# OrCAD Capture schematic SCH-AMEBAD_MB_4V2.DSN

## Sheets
1 P1_DC Power: size Custom; title: ARMEBA_MB; rev: 1.0; note: DC Power
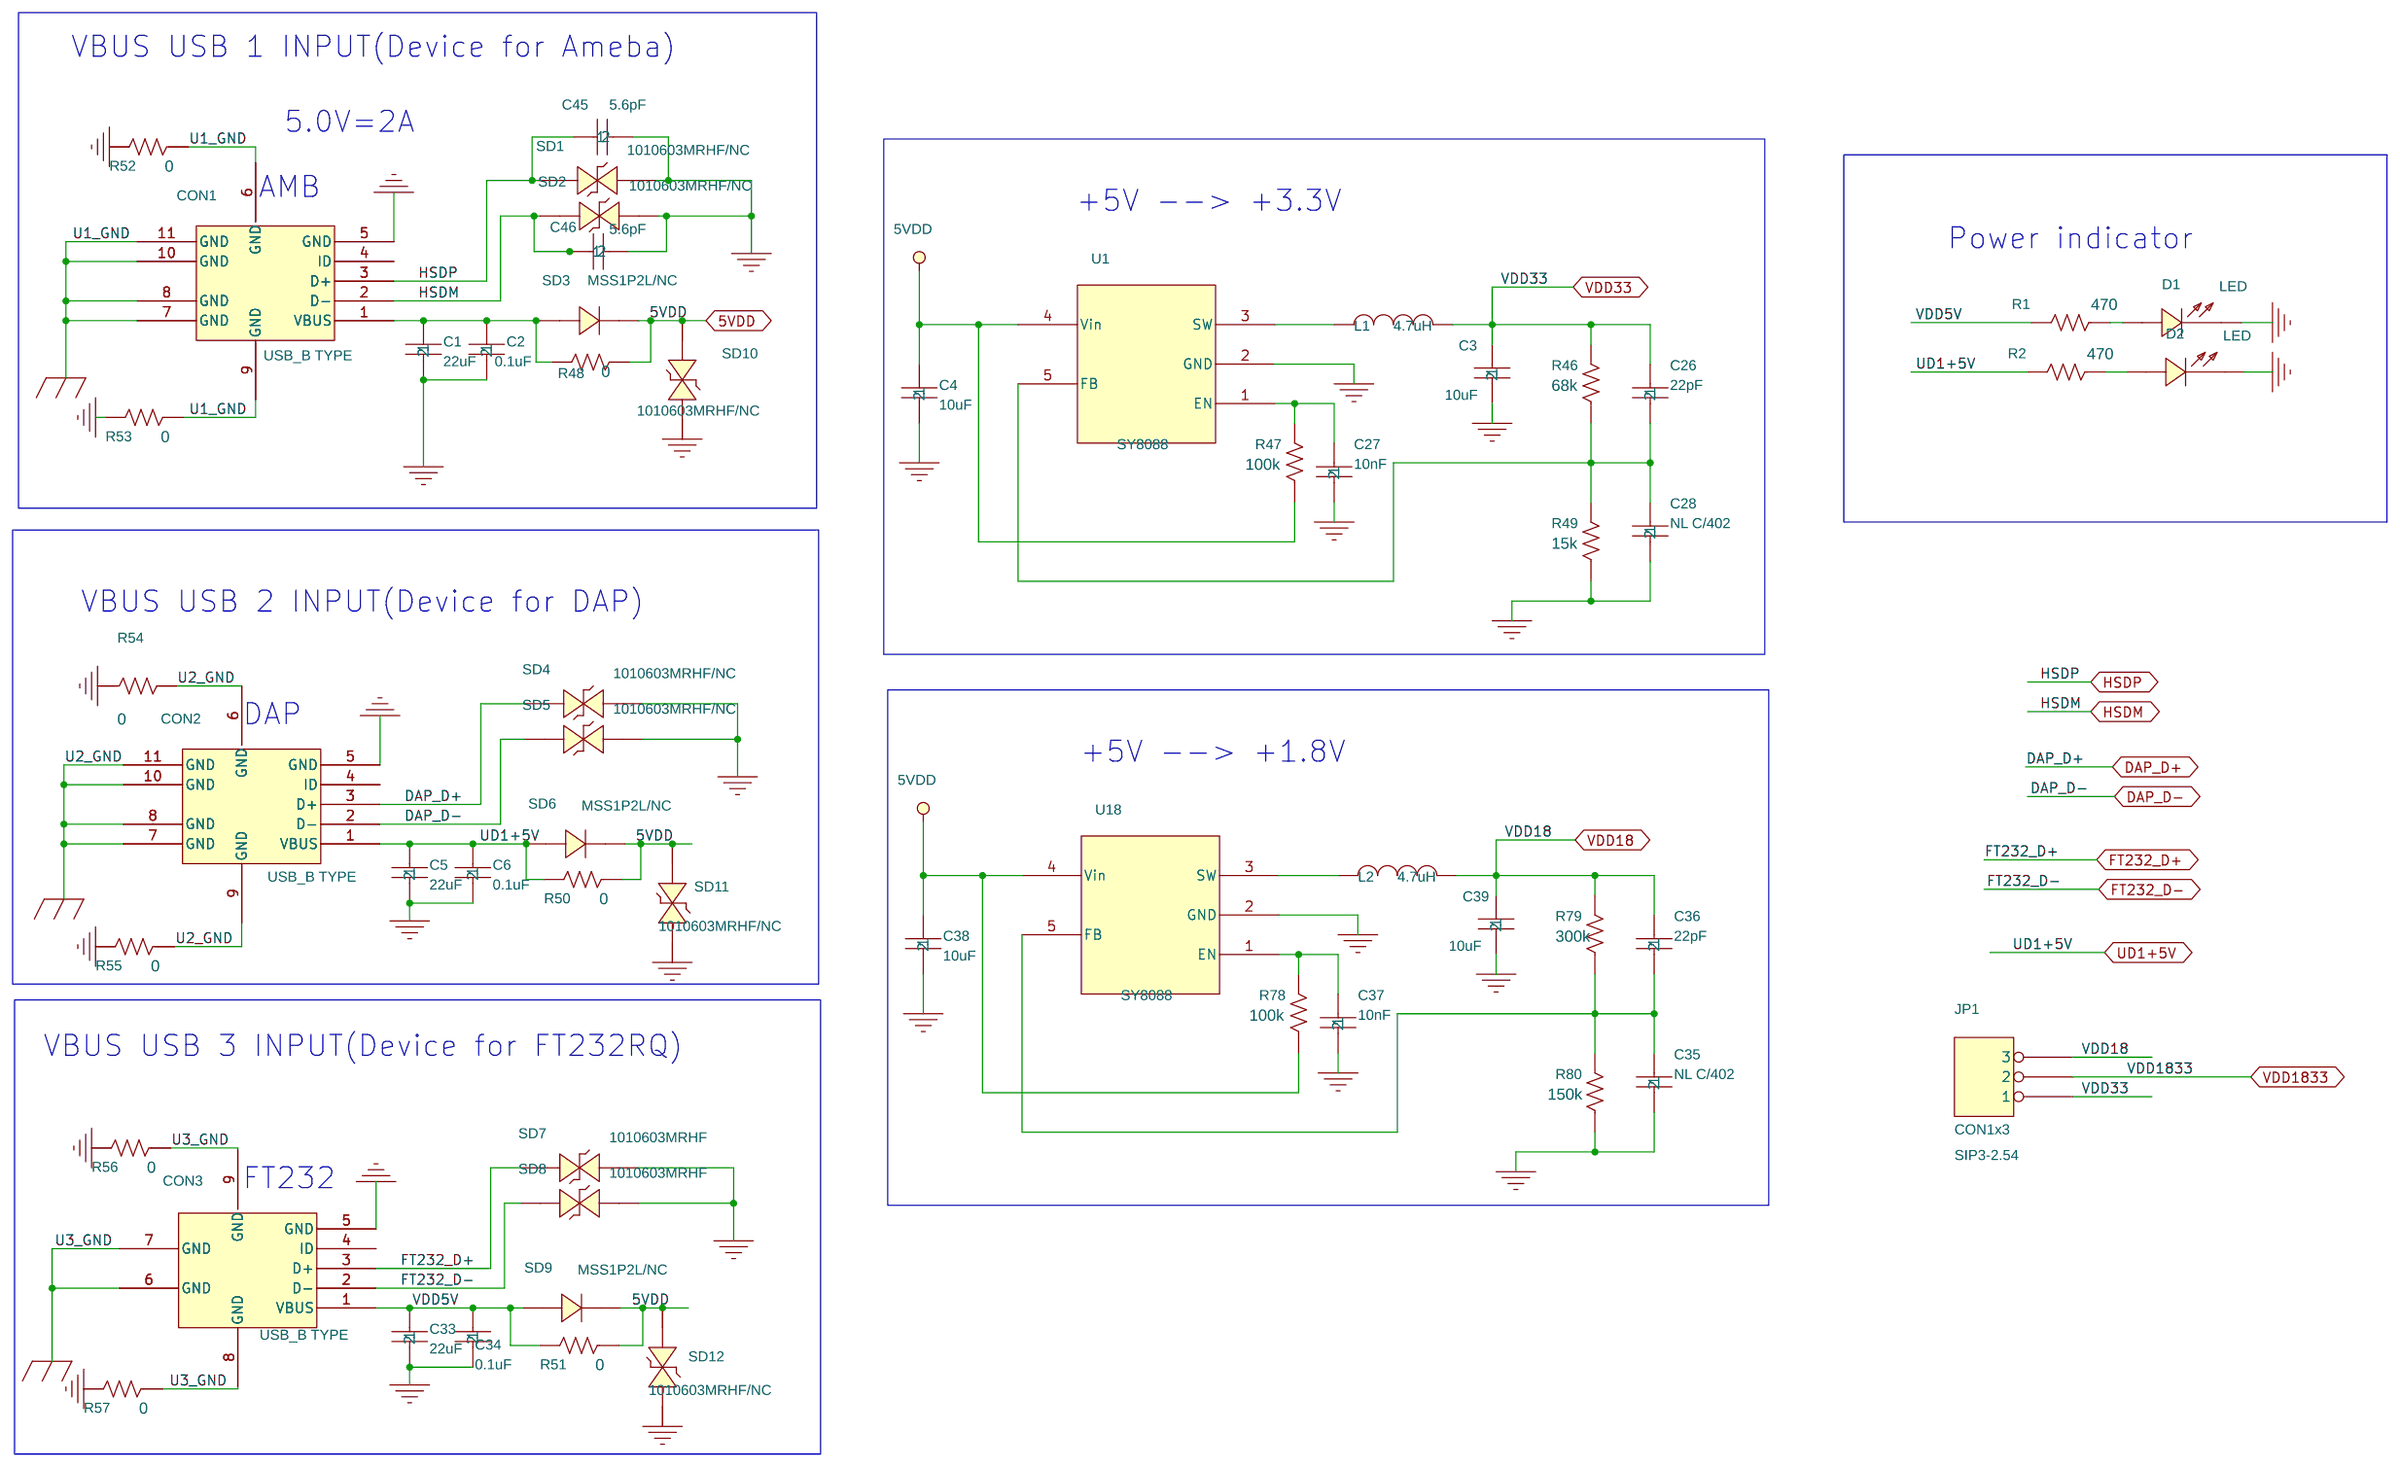
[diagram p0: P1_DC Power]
2 P2_Main: size Custom; title: ARDUINO; note: DAP/Ameba
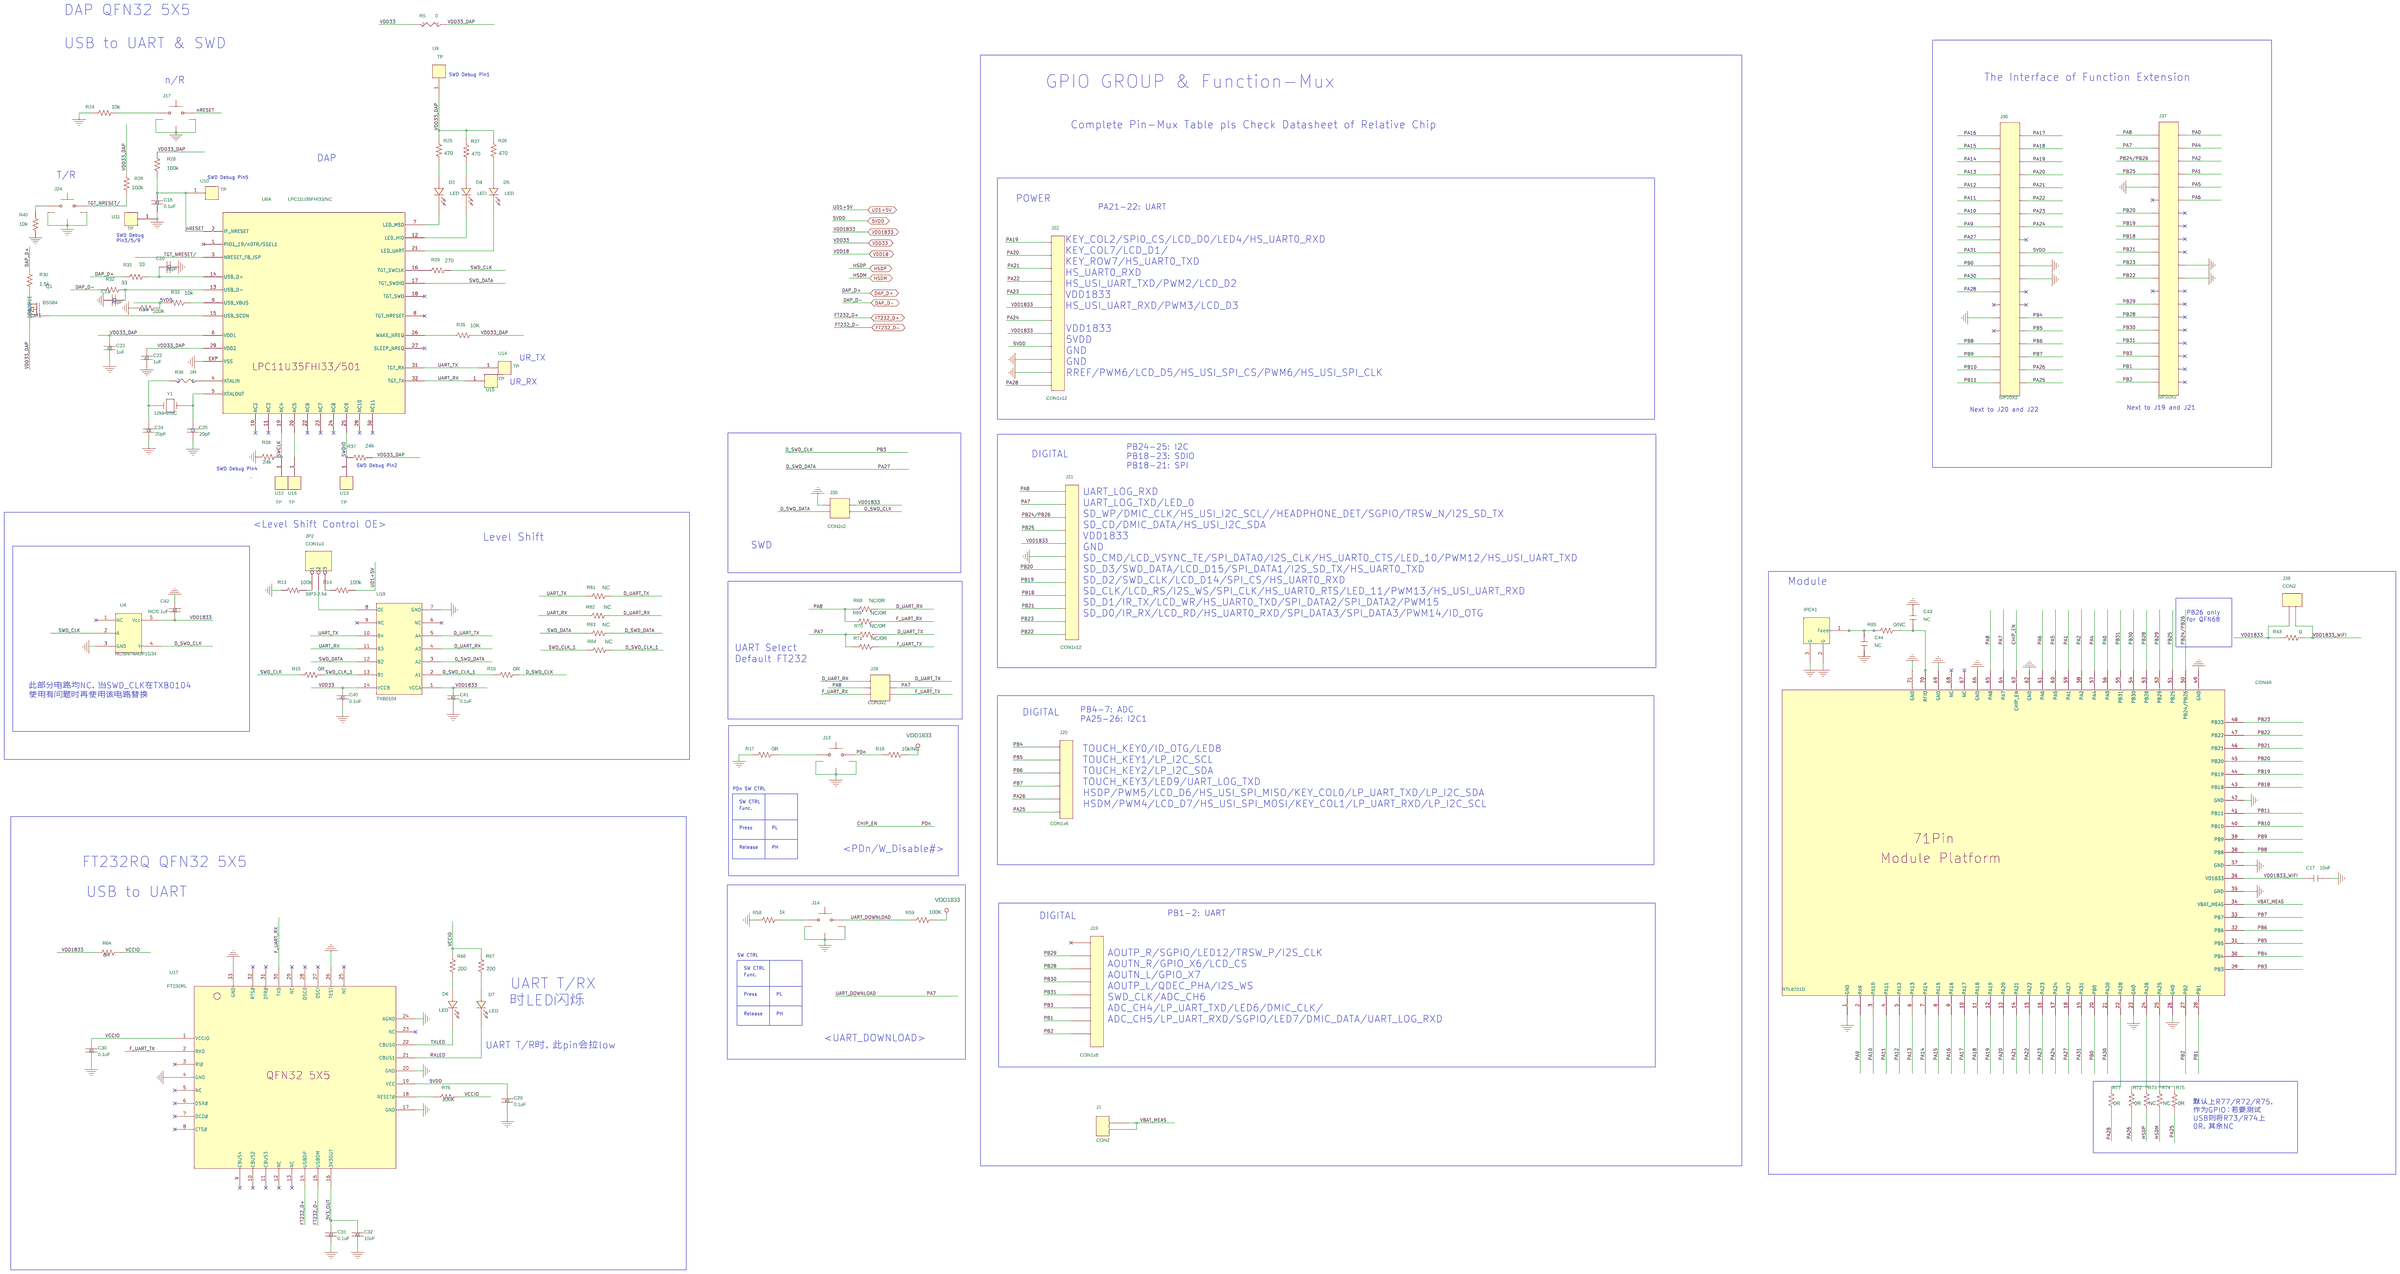
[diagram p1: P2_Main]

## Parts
sheet P1_DC Power
C1  22uF  [C0603]
C2  0.1uF  [C0402]
C3  10uF  [C0603]
C4  10uF  [C0603]
C5  22uF  [C0603]
C6  0.1uF  [C0402]
C26  22pF  [C0402]
C27  10nF  [C0402]
C28  NL C/402  [C0402]
C33  22uF  [C0603]
C34  0.1uF  [C0402]
C35  NL C/402  [C0402]
C36  22pF  [C0402]
C37  10nF  [C0402]
C38  10uF  [C0603]
C39  10uF  [C0603]
C45  5.6pF  [C0402]
C46  5.6pF  [C0402]
CON1  USB_B TYPE  [USB-MICRO-B-SMT-3]
CON2  USB_B TYPE  [USB-MICRO-B-SMT-3]
CON3  USB_B TYPE  [USB-MICRO-B-SMT-3]
D1  LED  [LED-0603]
D2  LED  [LED-0603]
JP1  CON1x3  [SIP3-2.54]
L1  4.7uH  [L3030]
L2  4.7uH  [L3030]
R1  470  [R0402]
R2  470  [R0402]
R46  68k  [R0402]
R47  100k  [R0402]
R48  0  [R0805]
R49  15k  [R0402]
R50  0  [R0805]
R51  0  [R0805]
R52  0  [R0603]
R53  0  [R0603]
R54  0  [R0603]
R55  0  [R0603]
R56  0  [R0603]
R57  0  [R0603]
R78  100k  [R0402]
R79  300k  [R0402]
R80  150k  [R0402]
SD1  1010603MRHF/NC  [L0603]
SD2  1010603MRHF/NC  [L0603]
SD3  MSS1P2L/NC  [MICROSMP]
SD4  1010603MRHF/NC  [L0603]
SD5  1010603MRHF/NC  [L0603]
SD6  MSS1P2L/NC  [MICROSMP]
SD7  1010603MRHF  [L0603]
SD8  1010603MRHF  [L0603]
SD9  MSS1P2L/NC  [MICROSMP]
SD10  1010603MRHF/NC  [L0603]
SD11  1010603MRHF/NC  [L0603]
SD12  1010603MRHF/NC  [L0603]
U1  SY8088  [SOT-23-5]
U18  SY8088  [SOT-23-5]
sheet P2_Main
C17  10uF  [C0603]
C18  0.1uF  [C0402]
C20  22pF  [C0402]
C21  22pF  [C0402]
C22  1uF  [C0402]
C23  1uF  [C0402]
C24  20pF  [C0402]
C25  20pF  [C0402]
C29  0.1uF  [C0402]
C30  0.1uF  [C0402]
C31  0.1uF  [C0402]
C32  10uF  [C0603]
C40  0.1uF  [C0402]
C41  0.1uF  [C0402]
C42  NC/0.1uF  [C0402]
C43  NC  [C0402]
C44  NC  [C0402]
CON4  RTL8721D  [71PIN-MODULE-PLATFORM]  (section A)
D3  LED  [LED-0603]
D4  LED  [LED-0603]
D5  LED  [LED-0603]
D6  LED  [LED-0603]
D7  LED  [LED-0603]
IPEX1  TP  [IPEX-0.7X2.2-1.35]
J1  CON2  [SIP2-2.54]
J13  Reset Button  [SW5-4.65X2.3-H1.85]
J14  Reset Button  [SW5-4.65X2.3-H1.85]
J17  Reset Button  [SW5-4.65X2.3-H1.85]
J19  CON1x8  [SIP8-2.54]
J20  CON1x6  [SIP6-2.54]
J21  CON1x12  [SIP12-2.54]
J22  CON1x12  [SIP12-2.54]
J24  Reset Button  [SW5-4.65X2.3-H1.85]
J28  CON3x2  [SIP3X2-2.54]
J35  CON2x2  [SIP2X2-2.54]
J36  SIP20X2  [SIP20X2-2.54]
J37  SIP20X2  [SIP20X2-2.54]
J38  CON2  [SIP2-2.54]
JP2  CON1x3  [SIP3-2.54]
Q1  BSS84  [SOT-23-GDS]
R5  0  [R0603]
R13  100k  [R0402]
R14  100k  [R0402]
R15  0R  [R0402]
R16  0R  [R0402]
R17  0R  [R0402]
R18  10k/NC  [R0402]
R24  10k  [R0402]
R25  470  [R0402]
R26  470  [R0402]
R27  470  [R0402]
R28  100k  [R0402]
R29  270  [R0402]
R30  1.5k  [R0402]
R31  33  [R0402]
R32  33  [R0402]
R33  10k  [R0402]
R34  100k  [R0402]
R35  10K  [R0402]
R36  0R  [R0402]
R37  24k  [R0402]
R38  24k  [R0402]
R39  100k  [R0402]
R40  10k  [R0402]
R43  0  [R0603]
R58  1k  [R0402]
R59  100K  [R0402]
R64  0R  [R0402]
R66  200  [R0402]
R67  200  [R0402]
R68  NC/0R  [R0402]
R69  NC/0R  [R0402]
R70  NC/0R  [R0402]
R71  NC/0R  [R0402]
R72  0R  [R0402]
R73  NC  [R0402]
R74  NC  [R0402]
R75  0R  [R0402]
R76  100K  [R0402]
R77  0R  [R0402]
R81  NC  [R0402]
R82  NC  [R0402]
R83  NC  [R0402]
R84  NC  [R0402]
R85  0/NC  [R0402]
U4  NC/SN74AUP1G34  [SOT-23-5]
U8  LPC11U35FHI33/NC  [QFN32-0505-.5-H.85-E3.75]  (section A)
U9  TP  [TP]
U10  TP  [TP]
U11  TP  [TP]
U12  TP  [TP]
U13  TP  [TP]
U14  TP  [TP]
U15  TP  [TP]
U16  TP  [TP]
U17  FT232RL  [QFN32-0.5-5X5-EP3.2]
U19  TXB0104  [SOP14/5.6/0.65]
Y1  12MHz/NC  [XTAL-CRYSTAL]

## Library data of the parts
C1 = C_7: X7R, ∮10%, 10V; Manufacturer: WALSIN; Part Number: 0402B104K100CT; Unit Price(USD): 0.0008
C2 = C_5: X7R, ∮10%, 10V; Manufacturer: WALSIN; Part Number: 0402B104K100CT; Unit Price(USD): 0.0008
C3 = C_6: X7R, ∮10%, 10V; Manufacturer: WALSIN; Part Number: 0402B104K100CT; Unit Price(USD): 0.0008
C4 = C_11: X7R, ∮10%, 10V; Manufacturer: WALSIN; Part Number: 0402B104K100CT; Unit Price(USD): 0.0008
C5 = C: X7R, ∮10%, 10V; Manufacturer: WALSIN; Part Number: 0402B104K100CT; Unit Price(USD): 0.0008
C6 = C_1: X7R, ∮10%, 10V; Manufacturer: WALSIN; Part Number: 0402B104K100CT; Unit Price(USD): 0.0008
C26 = CAP_NP_2: NPO, ∮10%, 25V; Manufacturer: WALSIN; Part Number: 0402B103K250CT; Unit Price(USD): 0.00076
C27 = CAP_NP_4: NPO, ∮10%, 25V; Manufacturer: WALSIN; Part Number: 0402B103K250CT; Unit Price(USD): 0.00076
C28 = CAP_NP_5
C33 = C_8: X7R, ∮10%, 10V; Manufacturer: WALSIN; Part Number: 0402B104K100CT; Unit Price(USD): 0.0008
C34 = C_3: X7R, ∮10%, 10V; Manufacturer: WALSIN; Part Number: 0402B104K100CT; Unit Price(USD): 0.0008
C35 = CAP_NP_3
C36 = CAP_NP_1: NPO, ∮10%, 25V; Manufacturer: WALSIN; Part Number: 0402B103K250CT; Unit Price(USD): 0.00076
C37 = CAP_NP: NPO, ∮10%, 25V; Manufacturer: WALSIN; Part Number: 0402B103K250CT; Unit Price(USD): 0.00076
C38 = C_2: X7R, ∮10%, 10V; Manufacturer: WALSIN; Part Number: 0402B104K100CT; Unit Price(USD): 0.0008
C39 = C_9: X7R, ∮10%, 10V; Manufacturer: WALSIN; Part Number: 0402B104K100CT; Unit Price(USD): 0.0008
C45 = C_10: X7R, ∮10%, 10V; Manufacturer: WALSIN; Part Number: 0402B104K100CT; Unit Price(USD): 0.0008
C46 = C_4: X7R, ∮10%, 10V; Manufacturer: WALSIN; Part Number: 0402B104K100CT; Unit Price(USD): 0.0008
CON1 = USB_CON_1X4P_ACON_2: CONTECK/22133-4W21-01; Class: IO; Colay_Alternate: N/A; Colay_Group: N/A; Component_Name: USB CON 1X4P,M,A TYPE,R/A,SMT; Critical_Part: N; Data_Sheet: K:\DataSheet\12-CONNECTOR\1213-003Q000.zip; Database_Update: 2009/2/7; Device: hh_usb_1x4p_4hd_m_ra_lf3; Electric_SPE: WHITE; FPLIST: hh_usb_1x4p_4hd_m_ra_lf3,usb_1x4p_4hd_m_ra_lf3; Green_HF: GA; HsFlag: A000000000; Manufacture: CONTECK; Modify_data: 2011/11/03; Optional: N/A; Package_Type: SMD; Part Number: 1213-003Q000; Part Type: 12CONNECTOR\USB; Sourcer: ¶À±Ò©ú(LA0803562); Subsystem_ID: N/A; Symbol_pic: K:\Symbol_Pic\12-CONNECTOR\1213-003Q000_MID.zip; metal_fabrication: 000000X100
CON2 = USB_CON_1X4P_ACON_5: CONTECK/22133-4W21-01; Class: IO; Colay_Alternate: N/A; Colay_Group: N/A; Component_Name: USB CON 1X4P,M,A TYPE,R/A,SMT; Critical_Part: N; Data_Sheet: K:\DataSheet\12-CONNECTOR\1213-003Q000.zip; Database_Update: 2009/2/7; Device: hh_usb_1x4p_4hd_m_ra_lf3; Electric_SPE: WHITE; FPLIST: hh_usb_1x4p_4hd_m_ra_lf3,usb_1x4p_4hd_m_ra_lf3; Green_HF: GA; HsFlag: A000000000; Manufacture: CONTECK; Modify_data: 2011/11/03; Optional: N/A; Package_Type: SMD; Part Number: 1213-003Q000; Part Type: 12CONNECTOR\USB; Sourcer: ¶À±Ò©ú(LA0803562); Subsystem_ID: N/A; Symbol_pic: K:\Symbol_Pic\12-CONNECTOR\1213-003Q000_MID.zip; metal_fabrication: 000000X100
CON3 = USB_CON_1X4P_ACON_3: CONTECK/22133-4W21-01; Class: IO; Colay_Alternate: N/A; Colay_Group: N/A; Component_Name: USB CON 1X4P,M,A TYPE,R/A,SMT; Critical_Part: N; Data_Sheet: K:\DataSheet\12-CONNECTOR\1213-003Q000.zip; Database_Update: 2009/2/7; Device: hh_usb_1x4p_4hd_m_ra_lf3; Electric_SPE: WHITE; FPLIST: hh_usb_1x4p_4hd_m_ra_lf3,usb_1x4p_4hd_m_ra_lf3; Green_HF: GA; HsFlag: A000000000; Manufacture: CONTECK; Modify_data: 2011/11/03; Optional: N/A; Package_Type: SMD; Part Number: 1213-003Q000; Part Type: 12CONNECTOR\USB; Sourcer: ¶À±Ò©ú(LA0803562); Subsystem_ID: N/A; Symbol_pic: K:\Symbol_Pic\12-CONNECTOR\1213-003Q000_MID.zip; metal_fabrication: 000000X100
D1-D7 = LED_0
JP1 JP2 = HEADER_3
L1 L2 = L: GTSD32 power inductor; Manufacturer: び护; Part number: NRH2410T-4R7MN; Unit Price(USD): 0.11875
R1 R2 R25-R27 R48 R50-R57 R64 R66 R67 R72-R77 = RES_V: Manufacturer: WALSIN; Part Number: WR04X4700FTL; Unit Price(USD): 0.00032
R46 R49 R79 R80 = RES_V: Manufacturer: WALSIN; Part Number: WR04X3003FTL; Unit Price(USD): 0.00032
R14-R18 R24 R40 R43 R47 R58 R59 R78 R85 = RES_V: Manufacturer: WALSIN; Part Number: WR04X1003FTL; Unit Price(USD): 0.00032
SD1 SD2 SD4 SD5 SD7 SD8 SD10-SD12 = DIODE_SCHOTTKY_1_v2
SD3 SD6 SD9 = DIODE_SCHOTTKY_1
U1 U18 = LT1084-3_0.3
C17 C43 C44 = C_402
C18 = CAP_NP_11: NPO, ∮10%, 50V; Manufacturer: WALSIN; Part Number: 0402B102K500CT; Unit Price(USD): 0.00076
C20 = CAP_NP_6: NPO, ∮10%, 50V; Manufacturer: WALSIN; Part Number: 0402B102K500CT; Unit Price(USD): 0.00076
C21 = CAP_NP_9: NPO, ∮10%, 50V; Manufacturer: WALSIN; Part Number: 0402B102K500CT; Unit Price(USD): 0.00076
C22 = CAP_NP_1: NPO, ∮10%, 50V; Manufacturer: WALSIN; Part Number: 0402B102K500CT; Unit Price(USD): 0.00076
C23 = CAP_NP: NPO, ∮10%, 50V; Manufacturer: WALSIN; Part Number: 0402B102K500CT; Unit Price(USD): 0.00076
C24 = C_1: NPO, ∮5%, 50V; Manufacturer: WALSIN; Part Number: 0402N180J500LT; Unit Price(USD): 0.00076
C25 = C: NPO, ∮5%, 50V; Manufacturer: WALSIN; Part Number: 0402N180J500LT; Unit Price(USD): 0.00076
C29 = CAP_NP_10: NPO, ∮10%, 50V; Manufacturer: WALSIN; Part Number: 0402B102K500CT; Unit Price(USD): 0.00076
C30 = CAP_NP_5: NPO, ∮10%, 50V; Manufacturer: WALSIN; Part Number: 0402B102K500CT; Unit Price(USD): 0.00076
C31 = CAP_NP_4: NPO, ∮10%, 50V; Manufacturer: WALSIN; Part Number: 0402B102K500CT; Unit Price(USD): 0.00076
C32 = CAP_NP_7: NPO, ∮10%, 50V; Manufacturer: WALSIN; Part Number: 0402B102K500CT; Unit Price(USD): 0.00076
C40 = CAP_NP_3: NPO, ∮10%, 50V; Manufacturer: WALSIN; Part Number: 0402B102K500CT; Unit Price(USD): 0.00076
C41 = CAP_NP_8: NPO, ∮10%, 50V; Manufacturer: WALSIN; Part Number: 0402B102K500CT; Unit Price(USD): 0.00076
C42 = CAP_NP_2: NPO, ∮10%, 50V; Manufacturer: WALSIN; Part Number: 0402B102K500CT; Unit Price(USD): 0.00076
CON4 = 8723BS_9
IPEX1 = TP_3
J1 J38 = CON2
J13 J14 J17 J24 = BUTTON_(RST)_1
J19 = CON6_4
J20 = CON6_3
J21 J22 = CON6_0
J28 = CON6_2
J35 = CON6_5
J36 J37 = CON6_10
Q1 = MOSFET_P_DGS_0
R5 = R
R13 R28-R35 R37-R39 R68-R71 R81-R84 = RES_V: Manufacturer: WALSIN; Part Number: WR04X1002FTL; Unit Price(USD): 0.00032
R36 = R_1
U4 = 2N7002DW_1
U8 = 8723BS_6
U9-U16 = TP
U17 = RL5760_0
U19 = 2N7002DW_3
Y1 = CRYSTAL_0

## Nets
3V3_OUT: C31.1 C32.1 U17.16(3V3OUT)
5VDD: C4.1 C29.1 C38.1 J22.9 J36.20 R33.2 R34.1 R47.2 R48.2 R50.2 R51.2 R78.2 SD3.2 SD6.2 SD9.2 SD10.2(CATHODE) SD11.2(CATHODE) SD12.2(CATHODE) U1.4(Vin) U17.19(VCC) U18.4(Vin)
AGND: C1.2 C2.2 C3.2 C4.2 C5.2 C6.2 C17.2 C18.2 C20.2 C21.1 C22.2 C23.2 C24.1 C25.1 C27.2 C28.2 C29.2 C30.2 C31.2 C32.2 C33.2 C34.2 C35.2 C37.2 C38.2 C39.2 C40.2 C41.2 C42.1 C43.2 C44.1 C45.2 C46.2 CON1.5(GND) CON2.5(GND) CON3.5(GND) CON4.1(GND) CON4.23(GND) CON4.26(GND) CON4.35(GND) CON4.37(GND) CON4.42(GND) CON4.49(GND) CON4.62(GND) CON4.66(GND) CON4.69(GND) CON4.71(GND) D1.2 D2.2 IPEX1.2(G) IPEX1.3(G) J13.3 J13.4 J13.5 J14.3 J14.4 J14.5 J17.3 J17.4 J17.5 J21.6 J22.10 J22.11 J24.3 J24.4 J24.5 J35.1 J36.22 J36.24 J36.29 J37.9 J37.22 J37.24 R13.1 R17.1 R24.1 R34.2 R38.1 R40.1 R49.2 R52.1 R53.1 R54.2 R55.1 R56.1 R57.1 R58.2 R80.2 SD1.1(ANODE) SD2.1(ANODE) SD4.1(ANODE) SD5.1(ANODE) SD7.1(ANODE) SD8.1(ANODE) SD10.1(ANODE) SD11.1(ANODE) SD12.1(ANODE) U1.2(GND) U4.3(GND) U8.EXP(VSS) U11.1 U17.4(GND) U17.17(GND) U17.20(GND) U17.24(AGND) U17.26(TEST) U17.33(GND) U18.2(GND) U19.7(GND)
VBAT_MEAS: CON4.34(VBAT_MEAS) J1.1 J1.2
VCCIO: C30.1 R64.1 R66.2 R67.2 R76.1 U17.1(VCCIO)
VDD5V: C33.1 C34.1 CON3.1(VBUS) R1.1 R51.1 SD9.1
VDD18: C36.1 C39.1 JP1.3 L2.2 R79.1
VDD33: C3.1 C26.1 C40.1 JP1.1 L1.2 R5.2 R46.1 U19.14(VCCB)
VDD33_DAP: C22.1 C23.1 Q1.S(SOURCE) R5.1 R25.2 R26.2 R27.2 R28.1 R35.1 R37.1 R39.1 U8.6(VDD1) U8.29(VDD2) U9.1
VDD1833: C41.1 C42.2 J21.5 J22.6 J22.8 J35.2 J38.1 JP1.2 R18.2 R43.1 R59.2 R64.2 U4.5(Vcc) U19.1(VCCA)
VDD1833_WIFI: C17.1 CON4.36(VD1833) J38.2 R43.2
CHIP_EN: CON4.63(CHIP_EN) J13.1 R18.1
D_SWD_CLK: CON4.29(PB3) J19.6 J35.4 J37.35 R16.2 U4.4(Y)
D_SWD_CLK_1: R16.1 R84.1 U19.2(A1)
D_SWD_DATA: CON4.18(PA27) J35.3 J36.17 R83.1 U19.3(A2)
D_UART_RX: J28.1 R68.1 R82.1 U19.4(A3)
D_UART_TX: J28.2 R70.1 R81.1 U19.5(A4)
DAP_D+: CON2.3(D+) R30.1 R31.2 SD4.2(CATHODE)
DAP_D-: CON2.2(D-) R32.2 SD5.2(CATHODE)
F_UART_RX: J28.5 R69.1 U17.30(TXD)
F_UART_TX: J28.6 R71.1 U17.2(RXD)
FT232_D+: CON3.3(D+) SD7.2(CATHODE) U17.14(USBDP)
FT232_D-: CON3.2(D-) SD8.2(CATHODE) U17.15(USBDM)
HSDM: C46.1 CON1.2(D-) R74.1 SD2.2(CATHODE)
HSDP: C45.1 CON1.3(D+) R73.1 SD1.2(CATHODE)
nRESET: C18.1 J17.1 R28.2 U8.2(IF_NRESET) U10.1
PA0: CON4.56(PA0) J37.2
PA1: CON4.59(PA1) J37.8
PA2: CON4.58(PA2) J37.6
PA4: CON4.57(PA4) J37.4
PA5: CON4.60(PA5) J37.10
PA6: CON4.61(PA6) J37.12
PA7: CON4.64(PA7) J14.1 J21.2 J28.4 J37.3 R59.1 R70.2 R71.2
PA8: CON4.65(PA8) J21.1 J28.3 J37.1 R68.2 R69.2
PA9: CON4.2(PA9) J36.15
PA10: CON4.3(PA10) J36.13
PA11: CON4.4(PA11) J36.11
PA12: CON4.5(PA12) J36.9
PA13: CON4.6(PA13) J36.7
PA14: CON4.7(PA14) J36.5
PA15: CON4.8(PA15) J36.3
PA16: CON4.9(PA16) J36.1
PA17: CON4.10(PA17) J36.2
PA18: CON4.11(PA18) J36.4
PA19: CON4.12(PA19) J22.1 J36.6
PA20: CON4.13(PA20) J22.2 J36.8
PA21: CON4.14(PA21) J22.3 J36.10
PA22: CON4.15(PA22) J22.4 J36.12
PA23: CON4.16(PA23) J22.5 J36.14
PA24: CON4.17(PA24) J22.7 J36.16
PA25: J20.6 J36.40 R75.1
PA26: J20.5 J36.38 R72.1
PA28: J22.12 J36.25 R77.1
PA30: CON4.21(PA30) J36.23
PA31: CON4.19(PA31) J36.19
PB0: CON4.20(PB0) J36.21
PB1: CON4.28(PB1) J19.7 J37.37
PB2: CON4.27(PB2) J19.8 J37.39
PB4: CON4.30(PB4) J20.1 J36.30
PB5: CON4.31(PB5) J20.2 J36.32
PB6: CON4.32(PB6) J20.3 J36.34
PB7: CON4.33(PB7) J20.4 J36.36
PB8: CON4.38(PB8) J36.33
PB9: CON4.39(PB9) J36.35
PB10: CON4.40(PB10) J36.37
PB11: CON4.41(PB11) J36.39
PB18: CON4.43(PB18) J21.9 J37.17
PB19: CON4.44(PB19) J21.8 J37.15
PB20: CON4.45(PB20) J21.7 J37.13
PB21: CON4.46(PB21) J21.10 J37.19
PB22: CON4.47(PB22) J21.12 J37.23
PB23: CON4.48(PB23) J21.11 J37.21
PB24/PB26: CON4.50(PB24/PB26) J21.3 J37.5
PB25: CON4.51(PB25) J21.4 J37.7
PB28: CON4.53(PB28) J19.3 J37.29
PB29: CON4.52(PB29) J19.2 J37.27
PB30: CON4.54(PB30) J19.4 J37.31
PB31: CON4.55(PB31) J19.5 J37.33
RXLED: D7.2 U17.21(CBUS1)
SWCLK: R38.2 U8.19(NC4) U12.1
SWD_CLK: R15.1 R29.1 U4.2(A)
SWD_CLK_1: R15.2 R84.2 U19.13(B1)
SWD_DATA: R83.2 U8.17(TGT_SWDIO) U19.12(B2)
SWDIO: R37.2 U8.25(NC9) U13.1
TGT_NRESET/: J24.1 R39.2 U8.3(NRESET_FB_ISP)
TXLED: D6.2 U17.22(CBUS0)
U1_GND: CON1.6(GND) CON1.7(GND) CON1.8(GND) CON1.9(GND) CON1.10(GND) CON1.11(GND) R52.2 R53.2
U2_GND: CON2.6(GND) CON2.7(GND) CON2.8(GND) CON2.9(GND) CON2.10(GND) CON2.11(GND) R54.1 R55.2
U3_GND: CON3.6(GND) CON3.7(GND) CON3.8(GND) CON3.9(GND) R56.2 R57.2
UART_RX: R82.2 U8.32(TGT_TX) U15.1 U19.11(B3)
UART_TX: R81.2 U8.31(TGT_RX) U14.1 U19.10(B4)
UD1+5V: C5.1 C6.1 CON2.1(VBUS) R2.1 R14.2 R50.1 SD6.1
N26769: J24.2 R40.2
N97346: C1.1 C2.1 CON1.1(VBUS) R48.1 SD3.1
N16028450: U8.20(NC5) U16.1
N16076386: Q1.G(GATE) U8.15(USB_SCON)
N16083215: D6.1 R66.1
N16134528: R76.2 U17.18(RESET#)
N16626358: CON4.22(PA28) R77.2
N16627798: CON4.25(PA25) R74.2 R75.2
N16627923: CON4.24(PA26) R72.2 R73.2
N16633858: C35.1 C36.2 R79.2 R80.1 U18.5(FB)
N16633866: C37.1 R78.1 U18.1(EN)
N16633884: L2.1 U18.3(SW)
N16674372: J14.2 R58.1
N16706699: D7.1 R67.1
N16712250: JP2.3 R14.1
N16712260: JP2.1 R13.2
N16712456: JP2.2 U19.8(OE)
N16736043: C43.1 CON4.70(RFIO) R85.2
N16737620: C44.2 IPEX1.1(Feed) R85.1
N16739466: R29.2 U8.16(TGT_SWCLK)
N16918816: C26.2 C28.1 R46.2 R49.1 U1.5(FB)
N16918865: C27.1 R47.1 U1.1(EN)
N16919012: L1.1 U1.3(SW)
N17529015: J13.2 R17.2
N17887739: D3.2 U8.7(LED_MSD)
N17887785: D4.2 U8.12(LED_HID)
N17887833: D5.2 U8.21(LED_UART)
N17887893: D3.1 R25.1
N17887973: D4.1 R27.1
N17887987: D5.1 R26.1
N17888465: C24.2 R36.2 Y1.1
N17888941: C25.2 U8.5(XTALOUT) Y1.2
N17890386: R33.1 U8.9(USB_VBUS)
N17891457: Q1.D(DRAIN) R30.2
N17892115: C20.1 R31.1 U8.14(USB_D+)
N17892212: C21.2 R32.1 U8.13(USB_D-)
N17963528: D1.1 R1.2
N17963664: D2.1 R2.2
N17997319: R36.1 U8.4(XTALIN)
N17999431: R35.2 U8.26(WAKE_NREQ)
N18053609: J17.2 R24.2

Not connected (* = marked no-connect by the designer): CON1 4(ID); CON2 4(ID); CON3 4(ID); CON4 67(NC)* 68(NC)*; J19 1*; J36 18* 26* 27* 28* 31*; J37 11* 14* 16* 18* 20* 25* 26* 28* 30* 32* 34* 36* 38* 40*; U4 1(NC)*; U8 1(PIO1_19/nDTR/SSEL1)* 8(TGT_NRESET)* 10(NC2)* 11(NC3)* 18(TGT_SWO)* 22(NC6)* 23(NC7)* 24(NC8)* 27(SLEEP_NREQ)* 28(NC10)* 30(NC11)*; U17 3(RI#)* 5(NC)* 6(DSR#)* 7(DCD#)* 8(CTS#)* 9(CBUS4)* 10(CBUS2)* 11(CBUS3)* 12(NC)* 13(NC)* 23(NC)* 25(NC)* 27(OSCI)* 28(OSC0)* 29(NC)* 31(DTR#)* 32(RTS#)*; U19 6(NC)* 9(NC)*

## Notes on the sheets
sheet 1
- VBUS USB 1 INPUT(Device for Ameba)
- 5.0V=2A
- AMB
- +5V --> +3.3V
- Power indicator
- VBUS USB 2 INPUT(Device for DAP)
- DAP
- +5V --> +1.8V
- VBUS USB 3 INPUT(Device for FT232RQ)
- FT232
sheet 2
- DAP QFN32 5X5
- USB to UART & SWD
- SWD Debug Pin1
- The Interface of Function Extension
- n/R
- GPIO GROUP & Function-Mux
- Complete Pin-Mux Table pls Check Datasheet of Relative Chip
- DAP
- T/R
- SWD Debug Pin5
- POWER
- PA21-22: UART
- SWD Debug
  Pin3/5/9
- KEY_COL2/SPI0_CS/LCD_D0/LED4/HS_UART0_RXD
  KEY_COL7/LCD_D1/
  KEY_ROW7/HS_UART0_TXD
  HS_UART0_RXD
  HS_USI_UART_TXD/PWM2/LCD_D2
  VDD1833
  HS_USI_UART_RXD/PWM3/LCD_D3
- VDD1833
  5VDD
  GND
  GND
  RREF/PWM6/LCD_D5/HS_USI_SPI_CS/PWM6/HS_USI_SPI_CLK
- UR_TX
- UR_RX
- Next to J20 and J22
- Next to J19 and J21
- PB24-25: I2C
  PB18-23: SDIO
  PB18-21: SPI
- DIGITAL
- SWD Debug Pin2
- SWD Debug Pin4
- UART_LOG_RXD
  UART_LOG_TXD/LED_0
  SD_WP/DMIC_CLK/HS_USI_I2C_SCL//HEADPHONE_DET/SGPIO/TRSW_N/I2S_SD_TX
  SD_CD/DMIC_DATA/HS_USI_I2C_SDA
  VDD1833
  GND
  SD_CMD/LCD_VSYNC_TE/SPI_DATA0/I2S_CLK/HS_UART0_CTS/LED_10/PWM12/HS_USI_UART_TXD
  SD_D3/SWD_DATA/LCD_D15/SPI_DATA1/I2S_SD_TX/HS_UART0_TXD
  SD_D2/SWD_CLK/LCD_D14/SPI_CS/HS_UART0_RXD
  SD_CLK/LCD_RS/I2S_WS/SPI_CLK/HS_UART0_RTS/LED_11/PWM13/HS_USI_UART_RXD
  SD_D1/IR_TX/LCD_WR/HS_UART0_TXD/SPI_DATA2/SPI_DATA2/PWM15
  SD_D0/IR_RX/LCD_RD/HS_UART0_RXD/SPI_DATA3/SPI_DATA3/PWM14/ID_OTG
- <Level Shift Control OE>
- Level Shift
- SWD
- Module
- PB26 only
  for QFN68
- UART Select
  Default FT232
- 此部分电路均NC，当SWD_CLK在TXB0104
  使用有问题时再使用该电路替换
- DIGITAL
- PB4-7: ADC
  PA25-26: I2C1
- TOUCH_KEY0/ID_OTG/LED8
  TOUCH_KEY1/LP_I2C_SCL
  TOUCH_KEY2/LP_I2C_SDA
  TOUCH_KEY3/LED9/UART_LOG_TXD
  HSDP/PWM5/LCD_D6/HS_USI_SPI_MISO/KEY_COL0/LP_UART_TXD/LP_I2C_SDA
  HSDM/PWM4/LCD_D7/HS_USI_SPI_MOSI/KEY_COL1/LP_UART_RXD/LP_I2C_SCL
- PDn SW CTRL
- SW CTRL
- Func.
- Press
- PL
- Release
- PH
- <PDn/W_Disable#>
- FT232RQ QFN32 5X5
- USB to UART
- PB1-2: UART
- DIGITAL
- AOUTP_R/SGPIO/LED12/TRSW_P/I2S_CLK
  AOUTN_R/GPIO_X6/LCD_CS
  AOUTN_L/GPIO_X7
  AOUTP_L/QDEC_PHA/I2S_WS
  SWD_CLK/ADC_CH6
  ADC_CH4/LP_UART_TXD/LED6/DMIC_CLK/
  ADC_CH5/LP_UART_RXD/SGPIO/LED7/DMIC_DATA/UART_LOG_RXD
- SW CTRL
- SW CTRL
- UART T/RX
  时LED闪烁
- Func.
- Press
- PL
- Release
- PH
- UART T/R时，此pin会拉low
- <UART_DOWNLOAD>
- 默认上R77/R72/R75，
  作为GPIO；若要测试
  USB则将R73/R74上
  0R，其余NC
